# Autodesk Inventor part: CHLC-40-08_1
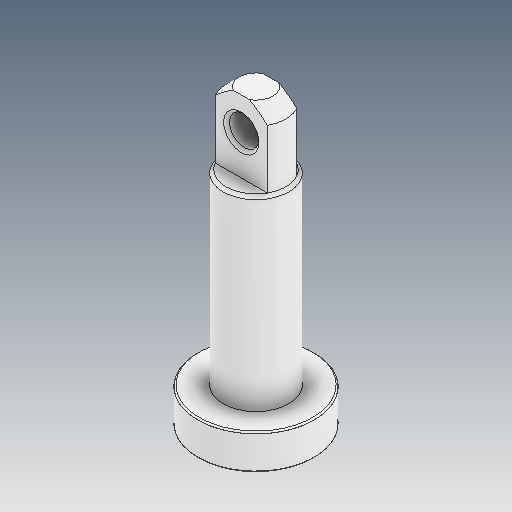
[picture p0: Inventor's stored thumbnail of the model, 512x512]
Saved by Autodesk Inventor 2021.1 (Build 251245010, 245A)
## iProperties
Created: 2021-05
Part Number: CHLC-40-08_1
Material: Ogólny
Document SubType Name: Modeling
Designer: user
Density: 1 g/cm^3
Appearance: Domyślna
Author: user
Revision Number: ÈÎºÎ
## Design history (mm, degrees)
feature "ÊäÈë1"
node "Bryła1"
